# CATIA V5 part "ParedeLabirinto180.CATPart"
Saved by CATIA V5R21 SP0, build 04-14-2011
Part number: ParedeLabirinto
Bounding box of the stored display mesh (mm): x 0 to 12, y 0 to 180, z 0 to 50
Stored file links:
  C:\Users\fisic\Desktop\labirinto catia\ParedeLabirinto180.CATPart
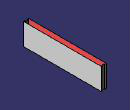
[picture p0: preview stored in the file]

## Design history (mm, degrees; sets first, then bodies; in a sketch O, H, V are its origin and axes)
Body1 (main body)
  Sketch1 on yz-plane, origin (0, 0, 0), H (0, 1, 0), V (0, 0, 1)
    line L1 (0, 0) -> (180, 0)
    line L2 (180, 0) -> (180, 50)
    line L3 (180, 50) -> (0, 50)
    line L4 (0, 50) -> (0, 0)
    point P2 (180, 50)
    distance P2 V = 180
    distance P2 H = 50
    horizontal: L1 H, L3 H
    vertical: L2 V, L4 V
  Pad1: profile Sketch1, direction (1, 0, 0), length 12
  Sketch2 on xy-plane, origin (0, 0, 0), H (1, 0, 0), V (0, 1, 0)
    point P1 (3.5, 0)
    line L1 (3.5, 0) -> (8.5, 0)
    line L2 (8.5, 0) -> (8.5, 2.5)
    line L3 (8.5, 2.5) -> (3.5, 2.5)
    line L4 (3.5, 2.5) -> (3.5, 0)
    line L5 (3.5, 180) -> (8.5, 180)
    line L6 (8.5, 180) -> (8.5, 177.5)
    line L7 (8.5, 177.5) -> (3.5, 177.5)
    line L8 (3.5, 177.5) -> (3.5, 180)
    reference projected line E1 (12, 180) -> (12, 0) from edge [face of Pad1 from Sketch1.L3 | end face of Pad1]
    reference projected line E2 (0, 180) -> (12, 180) from edge [face of Pad1 from Sketch1.L3 | face of Pad1 from Sketch1.L2]
    length L1 = 5
    length L2 = 2.5
    distance L4 V = 3.5
    length L5 = 5
    length L6 = 2.5
    distance L6 E1 = 3.5
    coincidence: P1 H, L5 E2, L1 H
    horizontal: L1 H, L3 H, L5 H, L7 H
    vertical: L2 V, L4 V, L6 V, L8 V
  Pocket1: profile Sketch2, direction (0, 0, -1), length -50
